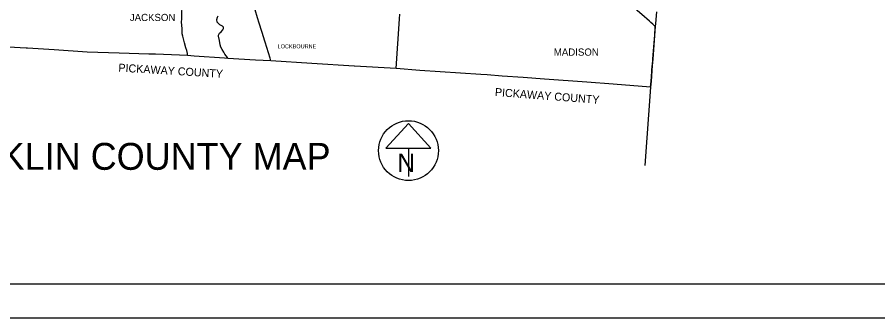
# Model space of a CAD drawing. Extents: x -1146 to -445, y -1283 to -822.
# Drawn here: x -959.3 to -690.7, y -1282.7 to -1188.9 of the extents above; entities that cross this region are included whole.
import ezdxf

# ---------------------------------------------------------------- set-up
doc = ezdxf.new("R2010")
doc.units = 0
for name, color, linetype in [('Default', 7, 'Continuous'), ('GM_X_Adjacent_County', 7, 'Continuous'), ('GM_X_Adjacent_County_Text', 7, 'Continuous'), ('GM_X_Corporation_Text', 7, 'Continuous'), ('GM_X_County', 7, 'Continuous'), ('GM_X_State_Route', 7, 'Continuous'), ('GM_X_Township', 7, 'Continuous'), ('GM_X_Township_Text', 7, 'Continuous'), ('GM_X_US_Route', 7, 'Continuous'), ('SH_Border', 7, 'Continuous'), ('SH_Cut_Line', 7, 'Continuous'), ('SH_Masking', 7, 'Continuous'), ('SH_Text', 7, 'Continuous')]:
    doc.layers.add(name, color=color, linetype=linetype)

msp = doc.modelspace()

# ---------------------------------------------------------------- linework, layer by layer
at = {"layer": 'GM_X_Adjacent_County'}
msp.add_line((-761.61, -1210.75), (-763.44, -1235.18), dxfattribs=at)
at = {"layer": 'GM_X_County'}
msp.add_lwpolyline([(-759.82, -1187.19), (-760.1, -1190.9), (-760.16, -1191.84), (-760.93, -1201.98), (-761.08, -1204.02), (-761.47, -1208.86), (-761.61, -1210.75), (-773.28, -1209.81), (-781.56, -1209.18), (-794.74, -1208.23), (-801.37, -1207.75), (-807.97, -1207.3), (-812.6, -1206.94), (-814.65, -1206.81), (-833.7, -1205.54), (-841.01, -1204.92), (-854.08, -1204.21), (-854.12, -1204.2), (-867.41, -1203.39), (-880.16, -1202.53), (-885, -1202.32), (-893.54, -1201.78), (-894.68, -1201.7), (-904.14, -1201.03), (-906.14, -1200.9), (-916.18, -1200.48), (-916.93, -1200.45), (-918.27, -1200.4), (-927.46, -1200.13), (-937.47, -1199.77), (-947.76, -1199.09), (-956.12, -1198.57), (-956.53, -1198.56), (-969.52, -1197.87)], dxfattribs=at)
at = {"layer": 'GM_X_State_Route'}
for points in [[(-906.14, -1200.9), (-906.23, -1200.26), (-906.42, -1199.27), (-906.7, -1198.46), (-907.12, -1196.87), (-907.66, -1194.81), (-907.8, -1194.13), (-907.89, -1192.48), (-908.01, -1190.48), (-907.99, -1189.4), (-907.96, -1187.77), (-907.89, -1185.72), (-907.89, -1185.71)], [(-760.16, -1191.84), (-760.97, -1191.06), (-761.53, -1190.55), (-761.98, -1190.17), (-762.01, -1190.14), (-764.37, -1188.1), (-766.44, -1186.28)], [(-760.35, -1194.38), (-760.18, -1192.11)], [(-760.18, -1192.11), (-760.16, -1191.84)], [(-761.07, -1203.95), (-760.93, -1201.98), (-760.35, -1194.38)], [(-761.36, -1207.48), (-761.08, -1204.02), (-761.07, -1203.95)], [(-761.61, -1210.75), (-761.47, -1208.86), (-761.36, -1207.48)]]:
    msp.add_lwpolyline(points, dxfattribs=at)
at = {"layer": 'GM_X_Township'}
for points in [[(-893.54, -1201.78), (-893.67, -1201.5), (-894.53, -1200.48), (-894.85, -1199.86), (-895.33, -1199.02), (-895.77, -1198.21), (-895.95, -1197.52), (-896.23, -1196.2), (-896.5, -1194.85), (-896.46, -1194.49), (-896.15, -1193.87), (-895.66, -1193.46), (-895.18, -1192.89), (-894.94, -1192.39), (-894.92, -1191.97), (-895.28, -1191.66), (-895.85, -1191.36), (-896.11, -1191.33), (-896.91, -1190.41), (-897, -1189.58), (-896.85, -1188.91), (-896.62, -1188.46)], [(-841.01, -1204.92), (-839.99, -1189.4), (-839.89, -1187.91)]]:
    msp.add_lwpolyline(points, dxfattribs=at)
at = {"layer": 'GM_X_US_Route'}
for points in [[(-884.32, -1189.07), (-885.09, -1186.6), (-885.79, -1183.98), (-885.8, -1183.58)], [(-882.15, -1196.12), (-882.37, -1195.39), (-883, -1193.38), (-883.82, -1190.74), (-884.32, -1189.07)], [(-880.16, -1202.53), (-880.42, -1201.72), (-881.98, -1196.69), (-882.15, -1196.12)]]:
    msp.add_lwpolyline(points, dxfattribs=at)
at = {"layer": 'SH_Border'}
msp.add_lwpolyline([(-1114.73, -832.23), (-455.34, -832.23), (-455.34, -1272.23), (-1114.73, -1272.23)], close=True, dxfattribs=at)
at = {"layer": 'SH_Cut_Line'}
msp.add_lwpolyline([(-1145.64, -1282.7), (-445.03, -1282.7), (-445.03, -821.75), (-1145.64, -821.75)], close=True, dxfattribs=at)
at = {"layer": 'SH_Masking'}
msp.add_circle((-837.21, -1230.55), 9.34, dxfattribs=at)
at = {"layer": 'SH_Text'}
for p, q in [((-837.21, -1222.03), (-844.22, -1229.81)), ((-830.2, -1229.81), (-837.21, -1222.03)), ((-844.22, -1229.81), (-830.2, -1229.81)), ((-837.21, -1229.81), (-837.21, -1238.62))]:
    msp.add_line(p, q, dxfattribs=at)
msp.add_circle((-837.21, -1230.55), 9.34, dxfattribs=at)

# ---------------------------------------------------------------- texts
at = {"layer": 'Default'}
msp.add_text('FRANKLIN COUNTY MAP', height=8.4, dxfattribs=at).set_placement((-995.08, -1236.53))
at = {"layer": 'GM_X_Adjacent_County_Text'}
for rotation, p in [(356.5821, (-927.81, -1205.88)), (355.6868, (-810.29, -1213.47))]:
    msp.add_text('PICKAWAY COUNTY', height=2.5, rotation=rotation, dxfattribs=at).set_placement(p)
at = {"layer": 'GM_X_Corporation_Text'}
msp.add_text('LOCKBOURNE', height=1.25, rotation=0, dxfattribs=at).set_placement((-878.06, -1198.62))
at = {"layer": 'GM_X_Township_Text'}
for s, p in [('JACKSON', (-924.18, -1190.11)), ('MADISON', (-791.83, -1200.92))]:
    msp.add_text(s, height=2.25, rotation=0, dxfattribs=at).set_placement(p)
at = {"layer": 'SH_Text'}
msp.add_text('N', height=5.7, dxfattribs=at).set_placement((-840.66, -1237.18))

doc.saveas('drawing.dxf')
